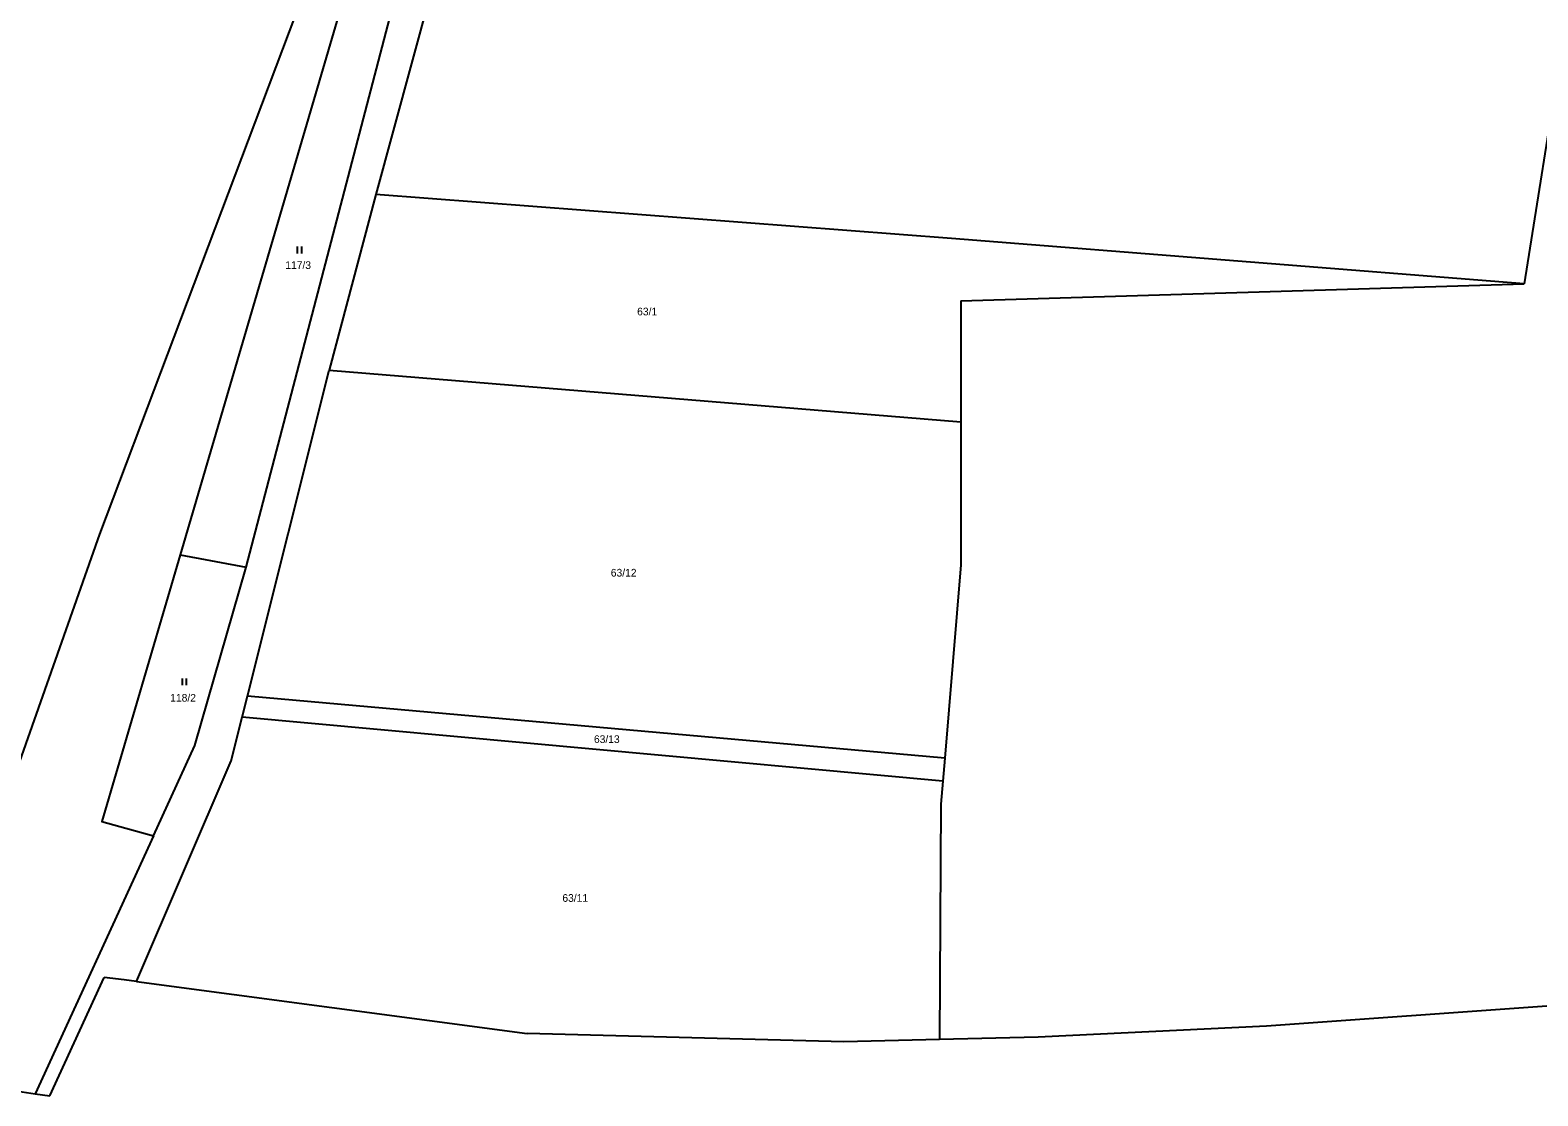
# Model space of a CAD drawing. Extents: x -752500 to -750336, y -1035826 to -1033500.
# Drawn here: x -752034.8 to -751701.2, y -1035482.2 to -1035246.4 of the extents above; entities that cross this region are included whole.
import ezdxf

# ---------------------------------------------------------------- set-up
doc = ezdxf.new("R2010")
doc.units = 0
for name, color, linetype in [('Default', 7, 'Continuous'), ('Hranice kat_území', 7, 'Continuous'), ('Hranice parcel', 7, 'Continuous'), ('Parcelní čísla', 7, 'Continuous'), ('Značky kultur', 7, 'Continuous')]:
    doc.layers.add(name, color=color, linetype=linetype)

# ---------------------------------------------------------------- blocks, each defined once
blk = doc.blocks.new('306')
at = {"layer": 'Default'}
for p, q in [((-0.5, 1.5), (-0.5, 0)), ((0.5, 0), (0.5, 1.5))]:
    blk.add_line(p, q, dxfattribs=at)

msp = doc.modelspace()

# ---------------------------------------------------------------- linework, layer by layer
at = {"layer": 'Hranice kat_území'}
for p, q in [((-752030.48, -1035482.16), (-752018.47, -1035455.97)), ((-752014.06, -1035456.51), (-752018.47, -1035455.97)), ((-752011.32, -1035456.85), (-752014.06, -1035456.51)), ((-752011.32, -1035456.85), (-751924.86, -1035468.38)), ((-751698.2, -1035462.25), (-751761.3, -1035466.73)), ((-751761.3, -1035466.73), (-751811.82, -1035469.21)), ((-751854.78, -1035470.18), (-751924.86, -1035468.38)), ((-751833.64, -1035469.7), (-751854.78, -1035470.18)), ((-751811.82, -1035469.21), (-751833.64, -1035469.7)), ((-752059, -1035477.87), (-752033.74, -1035481.68)), ((-752033.74, -1035481.68), (-752030.48, -1035482.16))]:
    msp.add_line(p, q, dxfattribs=at)
at = {"layer": 'Hranice parcel'}
for p, q in [((-751972.29, -1035232.78), (-752019.52, -1035357.91)), ((-751963.67, -1035233.09), (-752001.66, -1035362.46)), ((-751944.7, -1035232.59), (-751958.36, -1035282.73)), ((-751987.07, -1035365.19), (-751953.14, -1035235.55)), ((-751696.06, -1035251.03), (-751704.26, -1035302.52)), ((-751958.36, -1035282.73), (-751968.67, -1035321.63)), ((-751830.96, -1035292.49), (-751958.36, -1035282.73)), ((-751704.26, -1035302.52), (-751830.96, -1035292.49)), ((-751828.91, -1035306.31), (-751704.26, -1035302.52)), ((-751828.91, -1035306.31), (-751828.91, -1035333.06)), ((-751986.77, -1035393.76), (-751968.67, -1035321.63)), ((-751968.67, -1035321.63), (-751828.91, -1035333.06)), ((-751828.91, -1035333.06), (-751828.91, -1035364.7)), ((-752019.52, -1035357.91), (-752061.65, -1035477.47)), ((-752001.66, -1035362.46), (-751987.07, -1035365.19)), ((-751828.91, -1035364.7), (-751832.47, -1035407.49)), ((-751987.93, -1035398.4), (-751986.77, -1035393.76)), ((-751832.47, -1035407.49), (-751986.77, -1035393.76)), ((-751990.35, -1035408.04), (-751987.93, -1035398.4)), ((-751832.89, -1035412.54), (-751987.93, -1035398.4)), ((-751832.47, -1035407.49), (-751832.89, -1035412.54)), ((-752011.32, -1035456.85), (-751990.35, -1035408.04)), ((-751832.89, -1035412.54), (-751833.32, -1035417.65)), ((-751833.32, -1035417.65), (-751833.64, -1035469.7)), ((-752007.58, -1035424.66), (-752033.74, -1035481.68))]:
    msp.add_line(p, q, dxfattribs=at)
for points in [[(-752001.66, -1035362.46), (-752019, -1035421.5), (-752007.58, -1035424.66)], [(-752007.58, -1035424.66), (-751998.38, -1035404.62), (-751987.07, -1035365.19)]]:
    msp.add_lwpolyline(points, dxfattribs=at)

# ---------------------------------------------------------------- block references
at = {"layer": 'Značky kultur'}
for p in [(-751975.26, -1035295.78), (-752000.73, -1035391.31)]:
    msp.add_blockref('306', p, dxfattribs=at)

# ---------------------------------------------------------------- texts
at = {"layer": 'Parcelní čísla'}
for s, p in [('117/3', (-751978.39, -1035299.23)), ('63/1', (-751900.53, -1035309.5)), ('63/12', (-751906.36, -1035367.28)), ('118/2', (-752003.85, -1035394.95)), ('63/13', (-751910.09, -1035404.1)), ('63/11', (-751917.08, -1035439.24))]:
    msp.add_text(s, height=1.7, dxfattribs=at).set_placement(p)

doc.saveas('drawing.dxf')
